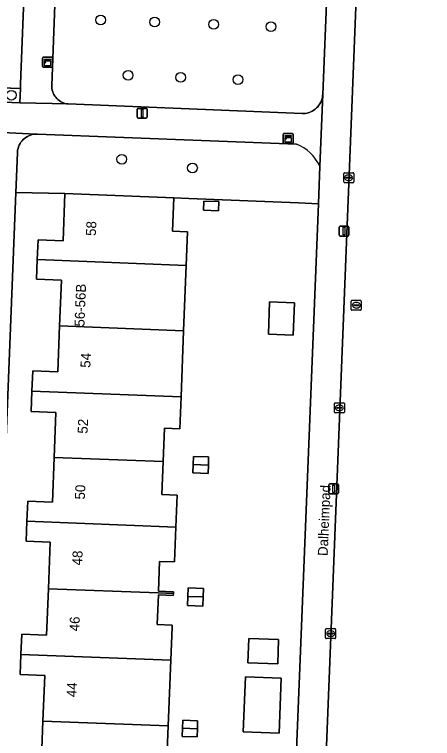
# Model space of a CAD drawing. Extents: x 160786 to 161429, y 386828 to 387485.
# Drawn here: x 161096.6 to 161138.7, y 387097.5 to 387170.3 of the extents above; entities that cross this region are included whole.
import ezdxf

# ---------------------------------------------------------------- set-up
doc = ezdxf.new("R2010")
doc.units = 0
for name, color, linetype in [('IMGEO_Boom', 7, 'Continuous'), ('IMGEO_Erf', 7, 'Continuous'), ('IMGEO_Groenvoorziening', 7, 'Continuous'), ('IMGEO_Haag', 7, 'Continuous'), ('IMGEO_Hek', 7, 'Continuous'), ('IMGEO_Kast', 7, 'Continuous'), ('IMGEO_Kolk', 7, 'Continuous'), ('IMGEO_Lichtmast', 7, 'Continuous'), ('IMGEO_Openbare_ruimte_label', 7, 'Continuous'), ('IMGEO_Pand', 7, 'Continuous'), ('IMGEO_Pand_nummerreeks', 7, 'Continuous'), ('IMGEO_Rioolput', 7, 'Continuous'), ('IMGEO_Voetpad_open', 7, 'Continuous')]:
    doc.layers.add(name, color=color, linetype=linetype)

msp = doc.modelspace()

# ---------------------------------------------------------------- linework, layer by layer
at = {"layer": 'IMGEO_Boom'}
for centre in [(161105.276, 387169.754), (161110.722, 387169.544), (161116.648, 387169.315), (161122.413, 387169.092), (161108.043, 387164.193), (161113.329, 387163.989), (161119.085, 387163.766), (161096.289, 387162.196), (161107.406, 387155.761), (161114.516, 387154.886)]:
    msp.add_circle(centre, 0.489, dxfattribs=at)
at = {"layer": 'IMGEO_Erf'}
for points in [[(161046.647, 387164.778), (161046.982, 387164.764), (161051.029, 387164.592), (161051.81, 387164.558), (161052.353, 387164.535), (161059.142, 387164.246), (161063.158, 387164.099), (161070.928, 387163.815), (161071.304, 387163.802), (161074.598, 387163.681), (161075.116, 387163.662), (161075.331, 387163.654), (161081.407, 387163.432), (161083.345, 387163.361), (161087.423, 387163.212), (161090.935, 387163.084), (161091.036, 387165.355), (161095.322, 387165.164), (161095.222, 387162.927), (161097.214, 387162.854), (161097.233, 387163.345), (161097.659, 387174.419)], [(161099.297, 387094.705), (161099.476, 387099.29), (161099.656, 387103.875), (161097.191, 387103.971), (161097.27, 387105.995), (161097.349, 387108.021), (161099.843, 387107.923), (161100.026, 387112.595), (161100.208, 387117.265), (161097.786, 387117.36), (161097.864, 387119.372), (161097.943, 387121.386), (161100.429, 387121.288), (161100.605, 387125.795), (161100.781, 387130.299), (161098.296, 387130.396), (161098.376, 387132.45), (161098.457, 387134.506), (161100.971, 387134.408), (161101.151, 387139.008), (161101.33, 387143.603), (161098.832, 387143.701), (161098.909, 387145.68), (161098.987, 387147.661), (161101.506, 387147.562), (161101.691, 387152.304), (161096.743, 387152.402), (161094.68, 387100.61)], [(161124.099, 387074.719), (161127.175, 387151.273), (161125.178, 387151.362), (161114.144, 387151.817), (161112.644, 387151.876), (161112.513, 387148.53), (161114.013, 387148.471), (161113.881, 387145.095), (161113.624, 387138.52), (161113.364, 387131.864), (161113.239, 387128.67), (161111.703, 387128.73), (161111.571, 387125.366), (161111.442, 387122.05), (161112.978, 387121.99), (161112.853, 387118.786), (161112.716, 387115.282), (161111.216, 387115.34), (161111.099, 387112.342), (161112.598, 387112.284), (161112.591, 387112.104), (161112.584, 387111.924), (161111.085, 387111.983), (161110.968, 387108.985), (161112.467, 387108.926), (161112.46, 387108.732), (161112.33, 387105.406), (161112.071, 387098.797), (161111.813, 387092.188)]]:
    msp.add_lwpolyline(points, dxfattribs=at)
for points in [[(161115.672, 387151.557), (161117.16, 387151.498), (161117.124, 387150.578), (161115.636, 387150.637)], [(161122.277, 387141.434), (161124.775, 387141.336), (161124.645, 387138.089), (161122.147, 387138.187)], [(161114.542, 387124.248), (161114.575, 387125.085), (161114.607, 387125.898), (161116.144, 387125.838), (161116.113, 387125.025), (161116.08, 387124.188)], [(161114, 387110.913), (161114.036, 387111.828), (161114.069, 387112.672), (161115.638, 387112.61), (161115.605, 387111.767), (161115.569, 387110.851)], [(161120.09, 387105.159), (161120.172, 387107.602), (161123.18, 387107.501), (161123.097, 387105.058)], [(161119.834, 387103.737), (161123.443, 387103.596), (161123.227, 387098.077), (161119.618, 387098.218)], [(161113.482, 387097.756), (161113.514, 387098.576), (161113.546, 387099.385), (161115.038, 387099.326), (161115.006, 387098.517), (161114.974, 387097.697)]]:
    msp.add_lwpolyline(points, close=True, dxfattribs=at)
at = {"layer": 'IMGEO_Groenvoorziening'}
for points in [[(161131.407, 387182.665), (161131.384, 387182.078), (161127.179, 387076.544), (161127.18, 387076.369), (161127.198, 387076.195), (161127.23, 387076.024), (161127.278, 387075.856), (161127.34, 387075.692), (161127.417, 387075.535), (161127.508, 387075.386), (161127.611, 387075.245), (161127.727, 387075.114), (161127.854, 387074.994), (161127.991, 387074.886), (161128.138, 387074.79), (161128.292, 387074.708), (161128.453, 387074.64), (161128.619, 387074.587), (161128.79, 387074.549), (161128.963, 387074.526), (161129.056, 387074.52), (161141.468, 387074.009), (161145.662, 387177.089)], [(161100.785, 387174.019), (161100.367, 387163.178), (161100.368, 387163.017), (161100.384, 387162.858), (161100.413, 387162.7), (161100.457, 387162.545), (161100.514, 387162.395), (161100.585, 387162.251), (161100.668, 387162.114), (161100.763, 387161.984), (161100.869, 387161.864), (161100.985, 387161.753), (161101.111, 387161.654), (161101.245, 387161.566), (161101.387, 387161.49), (161101.535, 387161.427), (161101.688, 387161.378), (161101.844, 387161.343), (161102.003, 387161.321), (161125.534, 387160.356), (161125.713, 387160.357), (161125.891, 387160.373), (161126.067, 387160.406), (161126.239, 387160.454), (161126.407, 387160.518), (161126.568, 387160.596), (161126.721, 387160.688), (161126.865, 387160.793), (161127, 387160.911), (161127.123, 387161.041), (161127.235, 387161.181), (161127.333, 387161.33), (161127.418, 387161.488), (161127.488, 387161.652), (161127.544, 387161.822), (161127.584, 387161.997), (161127.608, 387162.174), (161127.614, 387162.268), (161128.061, 387173.149)], [(161124.982, 387157.29), (161098.92, 387158.283), (161098.746, 387158.282), (161098.573, 387158.265), (161098.402, 387158.233), (161098.235, 387158.186), (161098.072, 387158.124), (161097.916, 387158.048), (161097.767, 387157.958), (161097.627, 387157.855), (161097.497, 387157.74), (161097.377, 387157.614), (161097.269, 387157.478), (161097.174, 387157.333), (161097.092, 387157.179), (161097.024, 387157.019), (161096.97, 387156.854), (161096.932, 387156.684), (161096.909, 387156.512), (161096.903, 387156.419), (161096.743, 387152.402), (161101.691, 387152.304), (161112.644, 387151.876), (161114.144, 387151.817), (161125.178, 387151.362), (161127.175, 387151.273), (161127.328, 387155.07)]]:
    msp.add_lwpolyline(points, dxfattribs=at)
msp.add_lwpolyline([(161097.214, 387162.854), (161095.222, 387162.927), (161095.214, 387162.739), (161090.928, 387162.93), (161090.935, 387163.084), (161087.423, 387163.212), (161087.364, 387161.825), (161097.16, 387161.441)], close=True, dxfattribs=at)
msp.add_arc((161123.303, 387153.167), 4.452, 25.31168, 67.8497, dxfattribs=at)
at = {"layer": 'IMGEO_Haag'}
msp.add_lwpolyline([(161097.214, 387162.854), (161087.423, 387163.212), (161087.364, 387161.825), (161097.16, 387161.441)], close=True, dxfattribs=at)
at = {"layer": 'IMGEO_Hek'}
msp.add_lwpolyline([(161097.214, 387162.854), (161087.423, 387163.212), (161083.345, 387163.361), (161081.407, 387163.432), (161075.331, 387163.654), (161075.116, 387163.662), (161074.598, 387163.681), (161071.304, 387163.802), (161070.928, 387163.815), (161063.158, 387164.099), (161059.142, 387164.246), (161052.353, 387164.535), (161051.029, 387164.592), (161046.982, 387164.764), (161046.647, 387164.778), (161038.81, 387165.111), (161034.783, 387165.283), (161026.6, 387165.631), (161022.975, 387165.785), (161022.636, 387165.799), (161014.462, 387166.146), (161011.004, 387166.293), (161000.917, 387166.722)], dxfattribs=at)
at = {"layer": 'IMGEO_Kast'}
for p, q in [((161099.438, 387165.094), (161099.438, 387165.935)), ((161099.438, 387165.935), (161099.438, 387165.094)), ((161099.513, 387166.019), (161100.354, 387166.019)), ((161100.354, 387166.019), (161099.513, 387166.019)), ((161100.438, 387165.944), (161100.438, 387165.103)), ((161100.438, 387165.103), (161100.438, 387165.944)), ((161100.363, 387165.019), (161099.522, 387165.019)), ((161099.522, 387165.019), (161100.363, 387165.019)), ((161123.637, 387157.414), (161123.637, 387158.255)), ((161123.637, 387158.255), (161123.637, 387157.414)), ((161123.712, 387158.339), (161124.553, 387158.339)), ((161124.553, 387158.339), (161123.712, 387158.339)), ((161124.637, 387158.264), (161124.637, 387157.423)), ((161124.637, 387157.423), (161124.637, 387158.264)), ((161124.562, 387157.339), (161123.721, 387157.339)), ((161123.721, 387157.339), (161124.562, 387157.339))]:
    msp.add_line(p, q, dxfattribs=at)
for points in [[(161099.633, 387165.809), (161100.233, 387165.809), (161100.233, 387165.724), (161099.633, 387165.724), (161099.633, 387165.809)], [(161099.633, 387165.634), (161100.233, 387165.634), (161100.233, 387165.145), (161099.633, 387165.145), (161099.633, 387165.634)], [(161123.832, 387158.129), (161124.432, 387158.129), (161124.432, 387158.044), (161123.832, 387158.044), (161123.832, 387158.129)], [(161123.832, 387157.954), (161124.432, 387157.954), (161124.432, 387157.465), (161123.832, 387157.465), (161123.832, 387157.954)]]:
    msp.add_lwpolyline(points, dxfattribs=at)
for centre in [(161099.717, 387165.483), (161123.916, 387157.803)]:
    msp.add_circle(centre, 0.0377, dxfattribs=at)
for centre, start, end in [((161099.516, 387165.941), 92.4484, 184.28452), ((161099.516, 387165.941), 92.4484, 184.28452), ((161100.36, 387165.941), 2.4484, 94.28452), ((161100.36, 387165.941), 2.4484, 94.28452), ((161099.516, 387165.097), 182.4484, 274.28452), ((161099.516, 387165.097), 182.4484, 274.28452), ((161100.36, 387165.097), 272.4484, 4.28452), ((161100.36, 387165.097), 272.4484, 4.28452), ((161123.715, 387158.261), 92.4484, 184.28452), ((161123.715, 387158.261), 92.4484, 184.28452), ((161124.559, 387158.261), 2.4484, 94.28452), ((161124.559, 387158.261), 2.4484, 94.28452), ((161123.715, 387157.417), 182.4484, 274.28452), ((161123.715, 387157.417), 182.4484, 274.28452), ((161124.559, 387157.417), 272.4484, 4.28452), ((161124.559, 387157.417), 272.4484, 4.28452)]:
    msp.add_arc(centre, 0.0779, start, end, dxfattribs=at)
at = {"layer": 'IMGEO_Kolk'}
for p, q in [((161129.733, 387153.477), (161129.733, 387154.329)), ((161129.808, 387154.403), (161130.66, 387154.403)), ((161129.992, 387153.897), (161129.992, 387153.909)), ((161130.43, 387153.86), (161130.032, 387153.86)), ((161130.035, 387153.946), (161130.433, 387153.946)), ((161130.221, 387154.183), (161130.246, 387154.183)), ((161130.476, 387153.909), (161130.476, 387153.897)), ((161130.734, 387154.329), (161130.734, 387153.477)), ((161130.66, 387153.403), (161129.808, 387153.403)), ((161130.244, 387153.623), (161130.219, 387153.623)), ((161128.792, 387130.349), (161128.792, 387131.201)), ((161128.867, 387131.275), (161129.719, 387131.275)), ((161129.793, 387131.201), (161129.793, 387130.349)), ((161129.051, 387130.769), (161129.051, 387130.781)), ((161129.489, 387130.732), (161129.091, 387130.732)), ((161129.094, 387130.818), (161129.492, 387130.818)), ((161129.303, 387130.495), (161129.278, 387130.495)), ((161129.28, 387131.055), (161129.305, 387131.055)), ((161129.535, 387130.781), (161129.535, 387130.769)), ((161129.719, 387130.275), (161128.867, 387130.275)), ((161127.981, 387108.581), (161128.833, 387108.581)), ((161127.906, 387107.655), (161127.906, 387108.507)), ((161128.165, 387108.075), (161128.165, 387108.087)), ((161128.603, 387108.038), (161128.205, 387108.038)), ((161128.208, 387108.124), (161128.606, 387108.124)), ((161128.394, 387108.361), (161128.419, 387108.361)), ((161128.649, 387108.087), (161128.649, 387108.075)), ((161128.907, 387108.507), (161128.907, 387107.655)), ((161128.833, 387107.581), (161127.981, 387107.581)), ((161128.417, 387107.801), (161128.392, 387107.801))]:
    msp.add_line(p, q, dxfattribs=at)
for points in [[(161129.733, 387153.477), (161129.733, 387154.329)], [(161129.808, 387154.403), (161130.66, 387154.403)], [(161130.734, 387154.329), (161130.734, 387153.477)], [(161130.66, 387153.403), (161129.808, 387153.403)], [(161128.792, 387130.349), (161128.792, 387131.201)], [(161128.867, 387131.275), (161129.719, 387131.275)], [(161129.793, 387131.201), (161129.793, 387130.349)], [(161129.719, 387130.275), (161128.867, 387130.275)], [(161127.981, 387108.581), (161128.833, 387108.581)], [(161127.906, 387107.655), (161127.906, 387108.507)], [(161128.907, 387108.507), (161128.907, 387107.655)], [(161128.833, 387107.581), (161127.981, 387107.581)]]:
    msp.add_lwpolyline(points, dxfattribs=at)
for centre, radius, start, end in [((161129.81, 387154.327), 0.0765, 91.55205, 178.44795), ((161129.81, 387154.327), 0.0765, 91.55205, 178.44795), ((161130.032, 387153.906), 0.0403, 85.87752, 175.75265), ((161130.029, 387153.896), 0.0366, 178.93798, 274.71019), ((161130.433, 387153.903), 0.043, 264.86636, 352.45326), ((161130.437, 387153.908), 0.0386, 1.73085, 96.63898), ((161130.658, 387154.327), 0.0765, 1.55205, 88.44795), ((161130.658, 387154.327), 0.0765, 1.55205, 88.44795), ((161129.81, 387153.479), 0.0765, 181.55205, 268.44795), ((161129.81, 387153.479), 0.0765, 181.55205, 268.44795), ((161130.658, 387153.479), 0.0765, 271.55205, 358.44795), ((161130.658, 387153.479), 0.0765, 271.55205, 358.44795), ((161128.869, 387131.199), 0.0765, 91.55205, 178.44795), ((161128.869, 387131.199), 0.0765, 91.55205, 178.44795), ((161129.717, 387131.199), 0.0765, 1.55205, 88.44795), ((161129.717, 387131.199), 0.0765, 1.55205, 88.44795), ((161129.091, 387130.778), 0.0403, 85.87752, 175.75265), ((161129.088, 387130.768), 0.0366, 178.93798, 274.71019), ((161129.492, 387130.775), 0.043, 264.86636, 352.45326), ((161129.496, 387130.78), 0.0386, 1.73085, 96.63898), ((161128.869, 387130.351), 0.0765, 181.55205, 268.44795), ((161128.869, 387130.351), 0.0765, 181.55205, 268.44795), ((161129.717, 387130.351), 0.0765, 271.55205, 358.44795), ((161129.717, 387130.351), 0.0765, 271.55205, 358.44795), ((161127.983, 387108.505), 0.0765, 91.55205, 178.44795), ((161127.983, 387108.505), 0.0765, 91.55205, 178.44795), ((161128.831, 387108.505), 0.0765, 1.55205, 88.44795), ((161128.831, 387108.505), 0.0765, 1.55205, 88.44795), ((161128.205, 387108.084), 0.0403, 85.87752, 175.75265), ((161128.202, 387108.074), 0.0366, 178.93798, 274.71019), ((161128.606, 387108.081), 0.043, 264.86636, 352.45326), ((161128.61, 387108.086), 0.0386, 1.73085, 96.63898), ((161127.983, 387107.657), 0.0765, 181.55205, 268.44795), ((161127.983, 387107.657), 0.0765, 181.55205, 268.44795), ((161128.831, 387107.657), 0.0765, 271.55205, 358.44795), ((161128.831, 387107.657), 0.0765, 271.55205, 358.44795)]:
    msp.add_arc(centre, radius, start, end, dxfattribs=at)
for centre, major_axis, ratio, start_param, end_param in [((161130.22, 387153.903), (-0.387, 0.002), 0.722429, 4.712389, 7.853982), ((161130.245, 387153.903), (-0.39, 0.002), 0.717154, 1.570796, 4.712389), ((161129.279, 387130.775), (-0.387, 0.002), 0.722429, 4.712389, 7.853982), ((161129.304, 387130.775), (-0.39, 0.002), 0.717154, 1.570796, 4.712389), ((161128.393, 387108.081), (-0.387, 0.002), 0.722429, 4.712389, 7.853982), ((161128.418, 387108.081), (-0.39, 0.002), 0.717154, 1.570796, 4.712389)]:
    msp.add_ellipse(centre, major_axis=major_axis, ratio=ratio, start_param=start_param, end_param=end_param, dxfattribs=at)
at = {"layer": 'IMGEO_Lichtmast'}
for p, q in [((161108.96, 387159.976), (161108.96, 387160.776)), ((161108.96, 387160.776), (161108.96, 387159.976)), ((161109.06, 387160.876), (161109.85, 387160.876)), ((161109.85, 387160.876), (161109.06, 387160.876)), ((161109.95, 387160.776), (161109.95, 387159.976)), ((161109.95, 387159.976), (161109.95, 387160.776)), ((161109.85, 387159.876), (161109.06, 387159.876)), ((161109.06, 387159.876), (161109.85, 387159.876)), ((161129.258, 387148.144), (161129.258, 387148.944)), ((161129.258, 387148.944), (161129.258, 387148.144)), ((161129.358, 387149.044), (161130.148, 387149.044)), ((161130.148, 387149.044), (161129.358, 387149.044)), ((161130.248, 387148.944), (161130.248, 387148.144)), ((161130.248, 387148.144), (161130.248, 387148.944)), ((161130.148, 387148.044), (161129.358, 387148.044)), ((161129.358, 387148.044), (161130.148, 387148.044)), ((161128.318, 387123.124), (161129.108, 387123.124)), ((161129.108, 387123.124), (161128.318, 387123.124)), ((161128.218, 387122.224), (161128.218, 387123.024)), ((161128.218, 387123.024), (161128.218, 387122.224)), ((161129.208, 387123.024), (161129.208, 387122.224)), ((161129.208, 387122.224), (161129.208, 387123.024)), ((161129.108, 387122.124), (161128.318, 387122.124)), ((161128.318, 387122.124), (161129.108, 387122.124))]:
    msp.add_line(p, q, dxfattribs=at)
for points in [[(161109.38, 387160.751), (161109.53, 387160.751), (161109.53, 387160.001), (161109.38, 387160.001), (161109.38, 387160.751)], [(161129.678, 387148.919), (161129.828, 387148.919), (161129.828, 387148.169), (161129.678, 387148.169), (161129.678, 387148.919)], [(161128.638, 387122.999), (161128.788, 387122.999), (161128.788, 387122.249), (161128.638, 387122.249), (161128.638, 387122.999)]]:
    msp.add_lwpolyline(points, dxfattribs=at)
for centre, start, end in [((161109.06, 387160.776), 90, 180), ((161109.06, 387160.776), 90, 180), ((161109.85, 387160.776), 0, 90), ((161109.85, 387160.776), 360, 90), ((161109.06, 387159.976), 180, 270), ((161109.06, 387159.976), 180, 270), ((161109.85, 387159.976), 270, 0), ((161109.85, 387159.976), 270, 0), ((161129.358, 387148.944), 90, 180), ((161129.358, 387148.944), 90, 180), ((161130.148, 387148.944), 0, 90), ((161130.148, 387148.944), 360, 90), ((161129.358, 387148.144), 180, 270), ((161129.358, 387148.144), 180, 270), ((161130.148, 387148.144), 270, 0), ((161130.148, 387148.144), 270, 0), ((161128.318, 387123.024), 90, 180), ((161128.318, 387123.024), 90, 180), ((161129.108, 387123.024), 0, 90), ((161129.108, 387123.024), 360, 90), ((161128.318, 387122.224), 180, 270), ((161128.318, 387122.224), 180, 270), ((161129.108, 387122.224), 270, 0), ((161129.108, 387122.224), 270, 0)]:
    msp.add_arc(centre, 0.1, start, end, dxfattribs=at)
at = {"layer": 'IMGEO_Pand'}
for points in [[(161112.644, 387151.876), (161101.691, 387152.304), (161101.506, 387147.562), (161098.987, 387147.661), (161098.909, 387145.68), (161113.881, 387145.095), (161114.013, 387148.471), (161112.513, 387148.53)], [(161115.636, 387150.637), (161117.124, 387150.578), (161117.16, 387151.498), (161115.672, 387151.557)], [(161113.881, 387145.095), (161098.909, 387145.68), (161098.832, 387143.701), (161101.33, 387143.603), (161101.151, 387139.008), (161113.624, 387138.52)], [(161124.775, 387141.336), (161122.277, 387141.434), (161122.147, 387138.187), (161124.645, 387138.089)], [(161101.151, 387139.008), (161100.971, 387134.408), (161098.457, 387134.506), (161098.376, 387132.45), (161113.364, 387131.864), (161113.624, 387138.52)], [(161113.364, 387131.864), (161098.376, 387132.45), (161098.296, 387130.396), (161100.781, 387130.299), (161100.605, 387125.795), (161111.571, 387125.366), (161111.703, 387128.73), (161113.239, 387128.67)], [(161111.571, 387125.366), (161100.605, 387125.795), (161100.429, 387121.288), (161097.943, 387121.386), (161097.864, 387119.372), (161112.853, 387118.786), (161112.978, 387121.99), (161111.442, 387122.05)], [(161114.575, 387125.085), (161116.113, 387125.025), (161116.144, 387125.838), (161114.607, 387125.898)], [(161116.113, 387125.025), (161114.575, 387125.085), (161114.542, 387124.248), (161116.08, 387124.188)], [(161112.853, 387118.786), (161097.864, 387119.372), (161097.786, 387117.36), (161100.208, 387117.265), (161100.026, 387112.595), (161111.055, 387112.164), (161112.591, 387112.104), (161112.598, 387112.284), (161111.099, 387112.342), (161111.216, 387115.34), (161112.716, 387115.282)], [(161112.591, 387112.104), (161111.055, 387112.164), (161100.026, 387112.595), (161099.843, 387107.923), (161097.349, 387108.021), (161097.27, 387105.995), (161112.33, 387105.406), (161112.46, 387108.732), (161112.467, 387108.926), (161110.968, 387108.985), (161111.085, 387111.983), (161112.584, 387111.924)], [(161114.036, 387111.828), (161115.605, 387111.767), (161115.638, 387112.61), (161114.069, 387112.672)], [(161115.605, 387111.767), (161114.036, 387111.828), (161114, 387110.913), (161115.569, 387110.851)], [(161120.09, 387105.159), (161123.097, 387105.058), (161123.18, 387107.501), (161120.172, 387107.602)], [(161097.27, 387105.995), (161097.191, 387103.971), (161099.656, 387103.875), (161099.476, 387099.29), (161112.071, 387098.797), (161112.33, 387105.406)], [(161119.618, 387098.218), (161123.227, 387098.077), (161123.443, 387103.596), (161119.834, 387103.737)], [(161111.813, 387092.188), (161112.071, 387098.797), (161099.476, 387099.29), (161099.297, 387094.705), (161096.813, 387094.802), (161096.734, 387092.778)], [(161113.514, 387098.576), (161115.006, 387098.517), (161115.038, 387099.326), (161113.546, 387099.385)], [(161115.006, 387098.517), (161113.514, 387098.576), (161113.482, 387097.756), (161114.974, 387097.697)]]:
    msp.add_lwpolyline(points, close=True, dxfattribs=at)
at = {"layer": 'IMGEO_Rioolput'}
for p, q in [((161130.484, 387140.657), (161130.484, 387141.509)), ((161130.559, 387141.583), (161131.411, 387141.583)), ((161130.972, 387141.363), (161130.997, 387141.363)), ((161131.485, 387141.509), (161131.485, 387140.657)), ((161131.411, 387140.583), (161130.559, 387140.583)), ((161130.743, 387141.077), (161130.743, 387141.089)), ((161131.181, 387141.04), (161130.783, 387141.04)), ((161130.786, 387141.126), (161131.184, 387141.126)), ((161130.995, 387140.803), (161130.97, 387140.803)), ((161131.227, 387141.089), (161131.227, 387141.077))]:
    msp.add_line(p, q, dxfattribs=at)
for points in [[(161130.484, 387140.657), (161130.484, 387141.509)], [(161130.559, 387141.583), (161131.411, 387141.583)], [(161131.485, 387141.509), (161131.485, 387140.657)], [(161131.411, 387140.583), (161130.559, 387140.583)]]:
    msp.add_lwpolyline(points, dxfattribs=at)
for centre, radius, start, end in [((161130.561, 387141.507), 0.0765, 91.55205, 178.44795), ((161130.561, 387141.507), 0.0765, 91.55205, 178.44795), ((161131.409, 387141.507), 0.0765, 1.55205, 88.44795), ((161131.409, 387141.507), 0.0765, 1.55205, 88.44795), ((161130.561, 387140.659), 0.0765, 181.55205, 268.44795), ((161130.561, 387140.659), 0.0765, 181.55205, 268.44795), ((161130.783, 387141.086), 0.0403, 85.87752, 175.75265), ((161130.78, 387141.076), 0.0366, 178.93798, 274.71019), ((161131.184, 387141.083), 0.043, 264.86636, 352.45326), ((161131.188, 387141.088), 0.0386, 1.73085, 96.63898), ((161131.409, 387140.659), 0.0765, 271.55205, 358.44795), ((161131.409, 387140.659), 0.0765, 271.55205, 358.44795)]:
    msp.add_arc(centre, radius, start, end, dxfattribs=at)
for centre, major_axis, ratio, start_param, end_param in [((161130.971, 387141.083), (-0.387, 0.002), 0.722429, 4.712389, 7.853982), ((161130.996, 387141.083), (-0.39, 0.002), 0.717154, 1.570796, 4.712389)]:
    msp.add_ellipse(centre, major_axis=major_axis, ratio=ratio, start_param=start_param, end_param=end_param, dxfattribs=at)
at = {"layer": 'IMGEO_Voetpad_open'}
for points in [[(161132.601, 387183.805), (161133.048, 387186.91), (161128.632, 387187.066), (161128.614, 387186.633), (161128.468, 387183.069), (161128.449, 387182.603), (161128.125, 387174.706), (161128.115, 387174.453), (161128.075, 387173.497), (161128.061, 387173.149), (161127.614, 387162.268), (161127.328, 387155.07), (161127.175, 387151.273), (161124.099, 387074.719)], [(161127.179, 387076.544), (161131.384, 387182.078)], [(161097.659, 387174.419), (161097.233, 387163.345), (161097.214, 387162.854), (161097.16, 387161.441), (161102.003, 387161.321), (161101.844, 387161.343), (161101.688, 387161.378), (161101.535, 387161.427), (161101.387, 387161.49), (161101.245, 387161.566), (161101.111, 387161.654), (161100.985, 387161.753), (161100.869, 387161.864), (161100.763, 387161.984), (161100.668, 387162.114), (161100.585, 387162.251), (161100.514, 387162.395), (161100.457, 387162.545), (161100.413, 387162.7), (161100.384, 387162.858), (161100.368, 387163.017), (161100.367, 387163.178), (161100.785, 387174.019)], [(161102.003, 387161.321), (161097.16, 387161.441), (161087.364, 387161.825), (161083.291, 387161.985), (161081.349, 387162.061), (161075.063, 387162.307), (161074.545, 387162.328), (161071.247, 387162.457), (161070.879, 387162.471), (161063.102, 387162.777), (161059.086, 387162.934), (161052.296, 387163.2), (161051.753, 387163.221), (161050.972, 387163.252), (161046.925, 387163.411), (161046.59, 387163.424)], [(161127.328, 387155.07), (161127.614, 387162.268), (161127.608, 387162.174), (161127.584, 387161.997), (161127.544, 387161.822), (161127.488, 387161.652), (161127.418, 387161.488), (161127.333, 387161.33), (161127.235, 387161.181), (161127.123, 387161.041), (161127, 387160.911), (161126.865, 387160.793), (161126.721, 387160.688), (161126.568, 387160.596), (161126.407, 387160.518), (161126.239, 387160.454), (161126.067, 387160.406), (161125.891, 387160.373), (161125.713, 387160.357), (161125.534, 387160.356), (161102.003, 387161.321)], [(161094.68, 387100.61), (161096.743, 387152.402), (161096.903, 387156.419), (161096.909, 387156.512), (161096.932, 387156.684), (161096.97, 387156.854), (161097.024, 387157.019), (161097.092, 387157.179), (161097.174, 387157.333), (161097.269, 387157.478), (161097.377, 387157.614), (161097.497, 387157.74), (161097.627, 387157.855), (161097.767, 387157.958), (161097.916, 387158.048), (161098.072, 387158.124), (161098.235, 387158.186), (161098.402, 387158.233), (161098.573, 387158.265), (161098.746, 387158.282), (161090.7, 387158.68)], [(161090.7, 387158.68), (161098.746, 387158.282), (161098.92, 387158.283), (161124.982, 387157.29)]]:
    msp.add_lwpolyline(points, dxfattribs=at)
msp.add_arc((161123.303, 387153.167), 4.452, 25.31168, 67.8497, dxfattribs=at)

# ---------------------------------------------------------------- texts
at = {"layer": 'IMGEO_Openbare_ruimte_label'}
msp.add_text('Dalheimpad', height=1, rotation=87.64984, dxfattribs=at).set_placement((161128.114, 387115.869))
at = {"layer": 'IMGEO_Pand_nummerreeks'}
for s, rotation, p in [('58', 87.59952, (161104.795, 387148.033)), ('56-56B', 87.7714, (161103.649, 387138.923)), ('54', 87.60171, (161104.24, 387134.786)), ('52', 87.59952, (161103.963, 387128.16)), ('50', 87.59952, (161103.685, 387121.543)), ('48', 87.59952, (161103.408, 387114.921)), ('46', 87.59952, (161103.131, 387108.296)), ('44', 87.60171, (161102.853, 387101.675))]:
    msp.add_text(s, height=1, rotation=rotation, dxfattribs=at).set_placement(p)

doc.saveas('drawing.dxf')
